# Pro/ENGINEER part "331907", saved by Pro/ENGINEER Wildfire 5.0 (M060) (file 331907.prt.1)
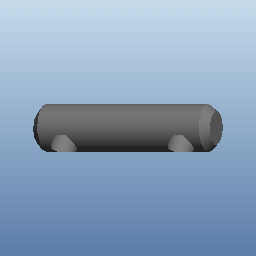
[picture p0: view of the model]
Units: PSOLunit; MM, KILOGRAM, SECS

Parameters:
  NN = "331907"
  NT = "Stainless Steel - Latch Clamps - 331-RSS Series - Pin"
  NB = "331907"
  NBSYN = "$PN."
  LINA = "331907"
  S = "331-rss"
  PN = "331907"
  ARTICLENO = "331907"
  BOMINFO = "331907"
  CREATOR = "CADENAS GmbH"

Other parameters: A1, A2, A3, A4, A5, A6, A7, NUTSIZE, SURF_AREA, MASS

Other named items: COORD, DEF-PLANE-AXIS, DEF-PLANE-AXIS-INV, CS0, DRILLING, CS1, DRILLING_1, B1_CSYS, B2_CSYS, F1_CSYS, F2_CSYS, PIN_TO_HANDLE_CSYS, PIN_TO_HOOK_CSYS, CONN, MASS, RIGHT, TOP, FRONT, B1_XPLN, B1_YPLN, B1_ZPLN, B2_XPLN, B2_YPLN, B2_ZPLN, F1_XPLN, F1_YPLN, F1_ZPLN, F2_XPLN, F2_YPLN, F2_ZPLN, PIN_TO_HANDLE_XPLN, PIN_TO_HANDLE_YPLN, PIN_TO_HANDLE_ZPLN, PIN_TO_HOOK_XPLN, PIN_TO_HOOK_YPLN, PIN_TO_HOOK_ZPLN, B1_ZAXS, B2_ZAXS, F1_ZAXS, F2_ZAXS, PIN_TO_HANDLE_ZAXS, PIN_TO_HOOK_ZAXS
